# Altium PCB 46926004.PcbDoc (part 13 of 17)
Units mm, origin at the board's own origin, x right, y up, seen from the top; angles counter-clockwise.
Board outline 250 x 200 mm, 6 copper layers (Top Layer, INT1_GND, INT2_SIG, INT3_SIG, INT4_GND, Bottom Layer), stack 1.71 mm thick; 1450 components, 1293 nets, 5656 pads, 2307 vias.
Unrouted connection lines stored in the file: 2.
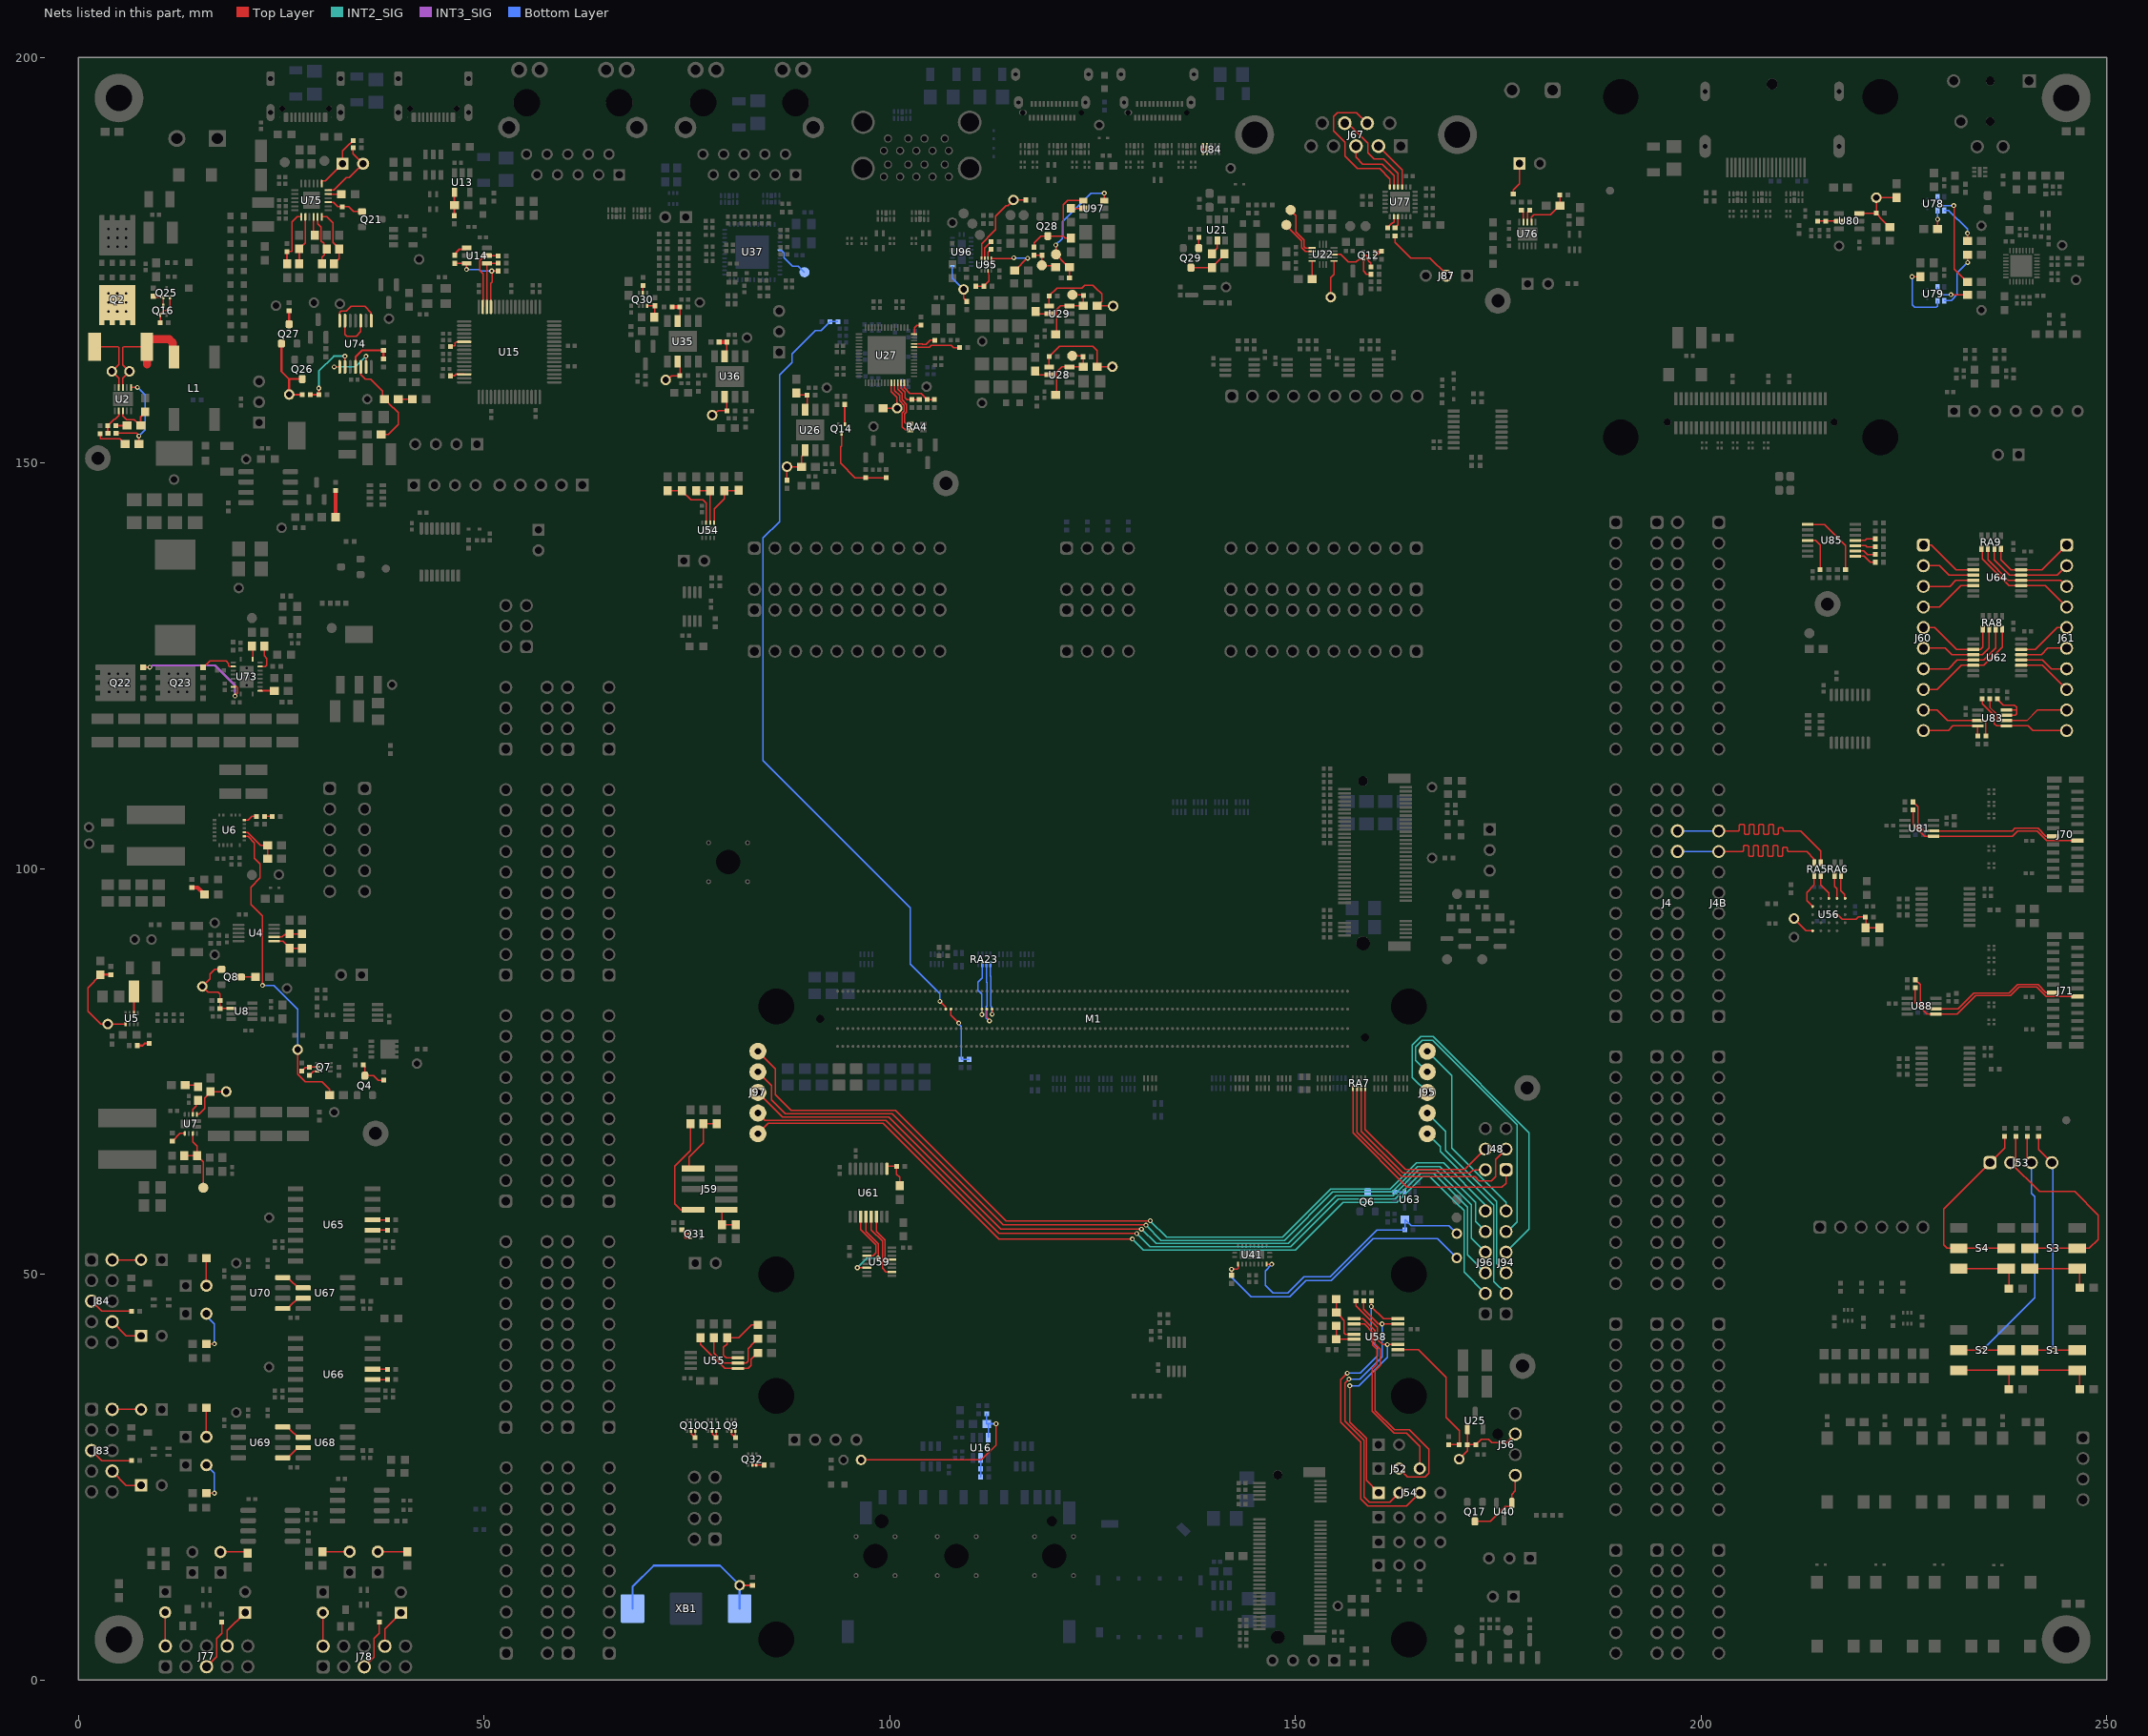
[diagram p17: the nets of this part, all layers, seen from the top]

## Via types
v1: diameter 0.6, hole 0.3, Top Layer to Bottom Layer, tented both sides, 2171 vias
v2: diameter 0.6, hole 0.3, Top Layer to Bottom Layer, 48 vias
v3: diameter 1, hole 0.5, Top Layer to Bottom Layer, tented both sides, 37 vias
v4: diameter 0.5, hole 0.2, Top Layer to Bottom Layer, tented both sides, 34 vias
v5: diameter 0.6, hole 0.3, Top Layer to Bottom Layer, tented bottom, 17 vias

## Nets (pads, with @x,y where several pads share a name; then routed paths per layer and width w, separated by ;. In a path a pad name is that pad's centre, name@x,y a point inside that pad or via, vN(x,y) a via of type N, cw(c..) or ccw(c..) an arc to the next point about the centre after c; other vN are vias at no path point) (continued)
NetJ45_2: J45.2 R206.2 | length 3.4
  Top Layer w0.15: R206.2@30.075,15.825 30.08,15.82 J45.2@33.434,15.82
NetJ48_1: J48.1 RA7.5 | length 29
  Top Layer w0.15: RA7.5@157.1,72.95 157.1,67.423 163.774,60.749 175.449,60.749 175.95,61.25 J48.1@175.95,62.895
NetJ48_2: J48.2 RA7.7 | length 22.9
  Top Layer w0.15: RA7.7@158.1,72.95 158.1,67.6 163.2,62.5 171.503,62.5 171.898,62.895 J48.2@173.41,62.895
NetJ48_3: J48.3 RA7.6 | length 29.1
  Top Layer w0.15: RA7.6@157.6,72.95 157.6,67.536 163.111,62.025 172.145,62.025 172.645,61.525 174.15,61.525 174.65,62.025 174.65,64.135 J48.3@175.95,65.435
NetJ48_4: J48.4 RA7.8 | length 23
  Top Layer w0.15: RA7.8@158.6,72.95 158.6,67.856 163.556,62.9 170.875,62.9 J48.4@173.41,65.435
NetJ49_2: J49.2 R207.2 | length 3.6
  Top Layer w0.15: J49.2@17.461,15.833 21.081,15.833 R207.2@21.086,15.838
NetJ52_2: J52.2 U58.9 | length 29.4
  Top Layer w0.15: U58.9@157.237,44.523 158.358,44.523 159.833,43.048 159.833,41.405 160.468,40.769 160.468,38.788 159.833,38.152 159.833,33.222 162.218,30.837 164.056,30.837 166.45,28.442 166.45,25.5 165.975,25.025 163.802,25.025 J52.2@162.777,26.05
NetJ52_3: J52.3 U58.10 | length 23.3
  Top Layer w0.15: U58.10@157.237,43.888 158.505,43.888 159.533,42.86 159.533,41.28 160.058,40.755 160.058,38.95 159.487,38.379 159.487,33.144 162.191,30.44 163.664,30.44 165.317,28.787 J52.3@165.317,26.05
NetJ53_1: J53.1 R259.2 S4.2 S4.5 | length 24.7
  Top Layer w0.15: S4.2@231.425,53.215 S4.5@237.925,53.215 ; S4.2@231.425,53.215 230.3,53.215 229.9,53.615 229.9,58.06 J53.1@235.615,63.775 237.4,65.56 R259.2@237.4,67
NetJ53_2: J53.2 R263.2 S3.2 S3.5 | length 29.2
  Top Layer w0.15: R263.2@238.8,67 238.8,64.42 J53.2@238.155,63.775 241.73,60.2 246.04,60.2 248.925,57.315 248.925,54.29 247.85,53.215 S3.2@240.175,53.215
NetJ53_3: J53.3 R257.2 S2.2 S2.5 | length 35.9
  Top Layer w0.15: S2.2@231.425,40.665 v1(234.675,40.665) S2.5@237.925,40.665 ; R257.2@240.2,67 240.2,64.27 J53.3@240.695,63.775
  Bottom Layer w0.15: v1(234.675,40.665) 241.125,47.115 241.125,59.55 240.695,59.98 J53.3@240.695,63.775
NetJ53_4: J53.4 R261.2 S1.2 S1.5 | length 33.6
  Top Layer w0.15: S1.2@240.175,40.665 S1.5@246.675,40.665 ; R261.2@241.6,67 241.6,65.41 J53.4@243.235,63.775
  Bottom Layer w0.15: J53.4@243.235,63.775 243.339,63.671 243.339,40.751 v1(243.425,40.665)
NetJ54_1: J54.1 R271.2 U58.3 | length 31
  Top Layer w0.15: v1(156.7,36.275) 156.7,31.811 158.736,29.775 158.736,24.589 J54.1@160.25,23.075 ; R271.2@157.461,46.743 157.461,46.139 160.133,43.467 160.133,41.952 160.738,41.347 v1(161.329,41.347) U58.3@162.637,41.347
  Bottom Layer w0.15: v1(156.7,36.275) 157.83,36.275 161.329,39.774 v1(161.329,41.347)
NetJ54_2: J54.2 R269.2 U58.7 | length 36.1
  Top Layer w0.15: v1(156.6,37.1) 156.114,36.614 156.114,31.893 158.436,29.571 158.436,22.589 159.1,21.925 161.64,21.925 J54.2@162.79,23.075 ; R269.2@158.411,46.743 158.411,45.71 160.233,43.888 U58.7@162.637,43.888
  Bottom Layer w0.15: v1(156.6,37.1) 157.956,37.1 160.681,39.825 v1(160.681,43.888)
NetJ54_3: J54.3 R268.2 U58.8 | length 40.8
  Top Layer w0.15: v1(156.383,37.824) 155.589,37.03 155.589,31.791 158.055,29.324 158.055,22.325 158.924,21.456 163.711,21.456 J54.3@165.33,23.075 ; R268.2@159.359,46.743 v1(159.359,46.033) 160.869,44.523 U58.8@162.637,44.523
  Bottom Layer w0.15: v1(156.383,37.824) 157.987,37.824 160.133,39.97 160.133,41.036 159.359,41.811 v1(159.359,46.033)
NetJ56_1: J56.1 Q17.3 U40.1 | length 9.2
  Top Layer w0.15: Q17.3@172.125,19.55 174.045,19.55 175.87,21.375 176.456,21.375 176.675,21.594 U40.1@176.675,21.8 176.675,22.875 177.1,23.3 J56.1@177.1,25.235
NetJ56_3: J56.3 R273.2 R274.1 U25.1 X80.1 | length 10.9
  Top Layer w0.15: X80.1@170.175,27.218 171.2,28.243 R273.2@171.2,29 ; U25.1@171.2,30.925 R273.2@171.2,29 ; J56.3@177.1,30.315 176.035,29.25 174.218,29.25 173.768,29.7 172.937,29.7 R274.1@172.237,29 R273.2@171.2,29
NetJ59_1: J59.1 R286.1 R287.1 | length 7.9
  Top Layer w0.15: J59.1@75.265,63.04 75.265,64.44 77.03,66.205 R286.1@77.03,68.55 R287.1@78.65,68.55
NetJ59_9: J59.9 R288.1 | length 12.7
  Top Layer w0.15: J59.9@75.265,57.96 74.24,57.96 73.5,58.7 73.5,63.358 75.425,65.283 R288.1@75.425,68.55
NetJ59_10: J59.10 R463.2 R464.2 | length 3.6
  Top Layer w0.15: J59.10@79.335,57.96 79.325,57.95 R464.2@79.325,56.1 R463.2@81.05,56.1
NetJ60_1: J60.1 U64.3 | length 7.1
  Top Layer w0.15: J60.1@227.4,139.88 228.395,139.88 231.425,136.85 U64.3@233.25,136.85
NetJ60_2: J60.2 U64.4 | length 6.3
  Top Layer w0.15: J60.2@227.4,137.34 229.385,137.34 230.525,136.2 U64.4@233.25,136.2
NetJ60_3: J60.3 U64.5 | length 6.2
  Top Layer w0.15: J60.3@227.4,134.8 230.65,134.8 231.4,135.55 U64.5@233.25,135.55
NetJ60_4: J60.4 U64.6 | length 6.9
  Top Layer w0.15: J60.4@227.4,132.26 229.385,132.26 232.025,134.9 U64.6@233.25,134.9
NetJ60_5: J60.5 RA8.1 U62.3 | length 10.8
  Top Layer w0.15: J60.5@227.4,129.72 228.78,129.72 231.475,127.025 233.25,127.025 234.425,127.025 234.712,127.312 RA8.1@234.712,129.525
NetJ60_6: J60.6 RA8.2 U62.4 | length 11.1
  Top Layer w0.15: J60.6@227.4,127.18 230.07,127.18 230.875,126.375 233.25,126.375 234.675,126.375 235.512,127.212 RA8.2@235.512,129.525
NetJ60_7: J60.7 RA8.3 U62.5 | length 12.3
  Top Layer w0.15: J60.7@227.4,124.64 230.49,124.64 231.575,125.725 233.25,125.725 234.85,125.725 236.312,127.187 RA8.3@236.312,129.525
NetJ60_8: J60.8 RA8.4 U62.6 | length 14.1
  Top Layer w0.15: J60.8@227.4,122.1 229.1,122.1 232.075,125.075 233.25,125.075 234.85,125.075 237.112,127.337 RA8.4@237.112,129.525
NetJ60_9: J60.9 R442.2 U83.3 | length 10.1
  Top Layer w0.15: J60.9@227.4,119.56 229.065,119.56 230.375,118.25 U83.3@234.105,118.25 234.107,118.248 234.952,118.248 235.1,118.1 R442.2@235.1,116.35
NetJ60_10: J60.10 R443.2 U83.4 | length 8.2
  Top Layer w0.15: J60.10@227.4,117.02 230.47,117.02 231.05,117.6 U83.4@234.105,117.6 234.105,116.355 R443.2@234.1,116.35
NetJ61_1: J61.1 RA9.4 U64.14 | length 11.2
  Top Layer w0.15: RA9.4@236.95,139.425 236.95,138.1 238.2,136.85 239.75,136.85 242.02,136.85 J61.1@245.05,139.88
NetJ61_2: J61.2 RA9.3 U64.13 | length 11.5
  Top Layer w0.15: RA9.3@236.15,139.425 236.15,138.05 238,136.2 239.75,136.2 243.91,136.2 J61.2@245.05,137.34
NetJ61_3: J61.3 RA9.2 U64.12 | length 12.4
  Top Layer w0.15: RA9.2@235.35,139.425 235.35,138.05 237.85,135.55 239.75,135.55 244.3,135.55 J61.3@245.05,134.8
NetJ61_4: J61.4 RA9.1 U64.11 | length 14.1
  Top Layer w0.15: RA9.1@234.55,139.425 234.653,139.322 234.653,138.216 237.969,134.9 239.75,134.9 242.41,134.9 J61.4@245.05,132.26
NetJ61_5: J61.5 U62.14 | length 6.4
  Top Layer w0.15: U62.14@239.75,127.025 241.175,127.025 243.87,129.72 J61.5@245.05,129.72
NetJ61_6: J61.6 U62.13 | length 5.6
  Top Layer w0.15: U62.13@239.75,126.375 241.925,126.375 242.73,127.18 J61.6@245.05,127.18
NetJ61_7: J61.7 U62.12 | length 5.7
  Top Layer w0.15: U62.12@239.75,125.725 242.075,125.725 243.16,124.64 J61.7@245.05,124.64
NetJ61_8: J61.8 U62.11 | length 6.5
  Top Layer w0.15: U62.11@239.75,125.075 242.075,125.075 J61.8@245.05,122.1
NetJ61_9: J61.9 R446.2 U83.6 | length 12.1
  Top Layer w0.18: R446.2@235.578,120.925 235.578,119.897 236.5,118.975 236.5,118.375 236.625,118.25 U83.6@237.645,118.25 240.15,118.25 241.46,119.56 J61.9@245.05,119.56
NetJ61_10: J61.10 R445.2 U83.5 | length 12.9
  Top Layer w0.15: R445.2@234.653,120.925 234.653,120.322 236.125,118.85 236.125,117.875 236.4,117.6 U83.5@237.645,117.6 240.325,117.6 240.905,117.02 J61.10@245.05,117.02
NetJ64_2: J64.2 R208.2 | length 3.6
  Top Layer w0.15: J64.2@36.9,15.82 40.52,15.82 R208.2@40.525,15.825
NetJ66_1: J66.1 R350.1 | length 4.1
  Top Layer w0.15: R350.1@176.855,183.15 176.855,183.682 177.605,184.432 J66.1@177.605,186.925
NetJ67_2: J67.2 U77.3 | length 6.1
  Top Layer w0.15: J67.2@160.235,189.06 163.15,186.145 U77.3@163.15,184.215
NetJ67_3: J67.3 U77.5 | length 8.2
  Top Layer w0.15: J67.3@157.465,189.06 157.465,187.697 158.302,186.86 160.714,186.86 162.15,185.424 U77.5@162.15,184.215
NetJ67_7: J67.7 U77.6 | length 17.9
  Top Layer w0.15: J67.7@158.85,191.9 157.54,193.21 155.171,193.21 154.695,192.734 154.695,190.946 156.121,189.52 156.121,187.817 157.651,186.287 160.398,186.287 161.65,185.035 U77.6@161.65,184.215
NetJ67_8: J67.8 U77.4 | length 11.3
  Top Layer w0.15: J67.8@156.08,191.9 156.484,191.9 158.95,189.434 158.95,188.247 159.697,187.5 160.849,187.5 162.65,185.699 U77.4@162.65,184.215
NetJ68_2: J68.2 R293.2 | length 4.9
  Top Layer w0.15: R293.2@15.77,41.447 R293.2@15.775,41.442 ; R293.2@15.773,41.445 v1(16.773,41.445)
  Bottom Layer w0.15: J68.2@15.77,44.9 16.773,43.898 v1(16.773,41.445)
NetJ70_13: J70.13 R364.2 U81.6 | length 20.6
  Top Layer w0.15: R364.2@226.12,108.23 226.724,107.625 226.724,105.416 227.475,104.665 U81.6@228.66,104.665 238.336,104.665 238.641,104.97 241.516,104.97 242.496,103.99 J70.13@243.4,103.99
NetJ70_14: J70.14 R365.2 U81.5 | length 23.4
  Top Layer w0.15: R365.2@226.12,107.24 226.12,105.435 227.54,104.015 U81.5@228.66,104.015 238.358,104.015 239.013,104.67 241.392,104.67 242.572,103.49 J70.14@246.4,103.49
NetJ71_13: J71.13 R372.2 U88.6 | length 21.4
  Top Layer w0.15: R372.2@226.404,86.305 227.009,85.7 227.009,83.491 227.759,82.74 U88.6@228.944,82.74 231.684,82.74 233.624,84.68 237.968,84.68 239.019,85.731 241.514,85.731 242.493,84.751 243.379,84.751 J71.13@243.4,84.73
NetJ71_14: J71.14 R373.2 U88.5 | length 24.3
  Top Layer w0.15: R373.2@226.404,85.315 226.404,83.51 227.825,82.09 U88.5@228.944,82.09 231.559,82.09 233.849,84.38 238.15,84.38 239.201,85.431 241.333,85.431 242.519,84.245 246.385,84.245 J71.14@246.4,84.23
NetJ73_2: J73.2 R295.2 | length 4.9
  Top Layer w0.15: R295.2@15.77,23.03 R295.2@15.775,23.025 ; R295.2@15.772,23.028 v1(16.772,23.028)
  Bottom Layer w0.15: J73.2@15.77,26.483 16.772,25.481 v1(16.772,23.028)
NetJ74_2: J74.2 R294.2 | length 3.6
  Top Layer w0.15: J74.2@15.77,48.383 15.77,51.962 R294.2@15.775,51.967
NetJ75_2: J75.2 R296.2 | length 3.6
  Top Layer w0.15: J75.2@15.77,29.966 15.77,33.545 R296.2@15.775,33.55
NetJ77_2: J77.2 J79.2 | length 4.1
  Top Layer w0.15: J79.2@10.686,8.318 10.701,8.303 10.701,4.198 J77.2@10.716,4.183
NetJ77_5: J77.5 R357.1 | length 6.3
  Top Layer w0.15: J77.5@15.796,1.643 17.011,2.858 17.011,5.113 17.661,5.763 R357.1@17.661,7.138
NetJ77_8: J77.8 J80.1 | length 5
  Top Layer w0.15: J77.8@18.336,4.183 18.336,6.098 J80.1@20.551,8.313
NetJ78_2: J78.2 J81.2 | length 4.1
  Top Layer w0.15: J81.2@30.125,8.305 30.14,8.29 30.14,4.185 J78.2@30.155,4.17
NetJ78_5: J78.5 R356.1 | length 6.3
  Top Layer w0.15: J78.5@35.235,1.63 36.45,2.845 36.45,5.1 37.1,5.75 R356.1@37.1,7.125
NetJ78_8: J78.8 J82.1 | length 4.9
  Top Layer w0.15: J78.8@37.775,4.17 37.775,6.3 J82.1@39.75,8.275
NetJ83_2: J83.2 J85.2 | length 3.6
  Top Layer w0.15: J83.2@4.163,33.363 4.169,33.356 7.723,33.356 J85.2@7.73,33.35
NetJ83_5: J83.5 R380.1 | length 5.4
  Top Layer w0.15: J83.5@1.623,28.283 2.856,27.05 R380.1@6.55,27.05
NetJ83_8: J83.8 J86.1 | length 4.3
  Top Layer w0.15: J83.8@4.163,25.743 5.906,24 J86.1@7.73,24
NetJ84_2: J84.2 J89.2 | length 3.6
  Top Layer w0.15: J84.2@4.163,51.78 4.173,51.79 7.72,51.79 J89.2@7.73,51.8
NetJ84_5: J84.5 R381.1 | length 5.4
  Top Layer w0.15: J84.5@1.623,46.7 2.856,45.467 R381.1@6.55,45.467
NetJ84_8: J84.8 J90.1 | length 4.3
  Top Layer w0.15: J84.8@4.163,44.16 5.906,42.417 J90.1@7.73,42.417
NetJ87_2: J87.2 R382.2 | length 8.9
  Top Layer w0.15: R382.2@162.275,178 162.275,177.224 164.234,175.265 166.59,175.265 168.6,173.255 J87.2@168.6,173.1
NetJ88_1: J88.1 R403.2 U75.13 | length 7.2
  Top Layer w0.15: U75.13@29.975,184.45 29.975,184.737 30.025,184.787 30.442,184.787 J88.1@32.555,186.9 32.555,188.473 33.457,189.375 33.475,189.375 R403.2@33.85,189.75
NetJ88_2: J88.2 R402.2 U75.12 | length 8.1
  Top Layer w0.15: U75.12@30.775,183.65 31.498,183.65 33.019,185.171 33.366,185.171 J88.2@35.095,186.9 33.85,188.145 R402.2@33.85,188.85
NetJ94_2: J94.2 J95.1 | length 23.7
  INT2_SIG w0.15: J95.1@166.25,67.34 167.847,65.743 167.847,65.153 174.469,58.531 174.469,49.136 J94.2@175.95,47.655
NetJ94_3: J94.3 J95.2 | length 23.7
  INT2_SIG w0.15: J95.2@166.25,69.88 168.506,67.624 168.506,65.29 174.8,58.996 174.8,51.345 J94.3@175.95,50.195
NetJ94_4: J94.4 J95.3 | length 42.2
  INT2_SIG w0.15: J95.3@166.25,72.42 164.4,74.27 164.4,78.256 165.436,79.292 166.98,79.292 178.8,67.471 178.8,55.585 J94.4@175.95,52.735
NetJ94_5: J94.5 J95.4 | length 34.7
  INT2_SIG w0.15: J95.4@166.25,74.96 164.8,76.41 164.8,78.05 165.624,78.874 166.906,78.874 177.34,68.44 177.34,56.49 176.125,55.275 J94.5@175.95,55.275
NetJ94_6: J94.6 J95.5 | length 23.7
  INT2_SIG w0.15: J95.5@166.25,77.5 169.25,74.5 169.25,65.55 175.95,58.85 J94.6@175.95,57.815
NetJ96_2: J96.2 J97.1 | length 110.8
  Top Layer w0.15: J97.1@83.75,67.34 85.024,68.614 99.187,68.614 113.434,54.367 v1(129.888,54.367)
  INT2_SIG w0.15: v1(129.888,54.367) 131.255,53 149.989,53 155.856,58.867 162.502,58.867 165.696,62.06 166.586,62.06 169.875,58.771 170.8,57.846 170.8,50.265 J96.2@173.41,47.655
NetJ96_3: J96.3 J97.2 | length 108.8
  Top Layer w0.15: J97.2@83.75,69.88 84.63,69 99.506,69 113.48,55.026 v1(130.45,55.026)
  INT2_SIG w0.15: v1(130.45,55.026) 132.076,53.4 149.426,53.4 155.312,59.285 162.289,59.285 165.449,62.446 167.054,62.446 171.2,58.3 171.2,52.405 J96.3@173.41,50.195
NetJ96_4: J96.4 J97.3 | length 107.7
  Top Layer w0.15: J97.3@83.75,72.42 86.77,69.4 99.893,69.4 113.718,55.575 v1(131.022,55.575)
  INT2_SIG w0.15: v1(131.022,55.575) 131.042,55.575 132.817,53.8 149.119,53.8 155.019,59.7 162.017,59.7 165.173,62.855 167.396,62.855 171.658,58.594 171.658,54.487 J96.4@173.41,52.735
NetJ96_5: J96.5 J97.4 | length 107.7
  Top Layer w0.15: J97.4@83.75,74.96 85.455,73.255 85.455,71.506 87.161,69.8 100.313,69.8 113.996,56.116 131.539,56.116 v1(131.583,56.072)
  INT2_SIG w0.15: v1(131.583,56.072) v1(131.583,56.072) 133.457,54.2 148.648,54.2 154.596,60.148 161.91,60.148 165.022,63.26 167.81,63.26 172.19,58.88 172.19,56.495 J96.5@173.41,55.275
NetJ96_6: J96.6 J97.5 | length 107.7
  Top Layer w0.15: J97.5@83.75,77.5 85.9,75.35 85.9,72.154 87.854,70.2 100.725,70.2 114.316,56.609 v1(132.108,56.609)
  INT2_SIG w0.15: v1(132.108,56.609) 134.116,54.6 148.412,54.6 154.329,60.517 161.719,60.517 164.945,63.743 168.257,63.743 173.41,58.59 J96.6@173.41,57.815
NetL1_2: L1.2 R8.1 U2.8 X109.1 | length 16.9
  Top Layer w0.15: U2.8@5.477,159.334 5.477,160.484 X109.1@6.293,161.3 5.477,162.116 5.477,164.259 5.565,164.347 R8.1@8.448,164.347
  Top Layer w1: 8.448,162.147 R8.1@8.448,164.347 8.448,165.247 11.204,165.247 11.65,164.801 11.65,163.212 L1.2@11.79,163.072
NetL5_1: L5.1 U5.6 | length 2.7
  Top Layer w0.25: U5.6@6.825,82.197 L5.1@6.825,84.85
NetM1_B78: M1.B78 R66.2 R459.2 | length 7.7
  Top Layer w0.15: M1.B78@107.537,82.7 107.537,81.94 v1(108.5,80.977)
  Bottom Layer w0.15: v1(108.5,80.977) 108.5,80.856 108.807,80.549 R66.2@108.807,76.507 ; R66.2@108.8,76.5 108.9,76.5 R459.2@109.8,76.5
NetM1_B79: M1.B79 R65.2 R352.1 | length 98.9
  Top Layer w0.15: v1(106.181,83.658) 106.886,82.954 106.886,82.716 M1.B79@106.902,82.7
  Bottom Layer w0.15: R65.2@93.622,167.443 R352.1@92.649,167.443 91.567,166.36 90.847,166.36 87.947,163.46 87.947,162.391 86.426,160.87 86.426,142.776 84.4,140.75 84.4,113.324 102.539,95.185 102.539,88.25 106.181,84.607 v1(106.181,83.658)
NetQ2_5: Q2.5 Q2.6 Q2.7 Q2.8 R8.2 U2.9 X108.1 | length 14.4
  Top Layer w0.15: R8.2@1.998,164.347 4.889,164.347 4.977,164.259 4.977,162.154 X108.1@4.123,161.3 4.977,160.446 U2.9@4.977,159.334
  Top Layer w0.25: Q2.5@2.89,167.324 Q2.5@2.89,167.371 2.89,168.059 3.187,168.357 3.548,168.357 3.595,168.404 4.096,167.903 4.096,167.388 Q2.6@4.16,167.324 ; Q2.8@4.79,168.404 5.328,167.866 5.328,167.426 Q2.7@5.43,167.324 ; Q2.8@5.985,168.404 6.052,168.337 6.313,168.337 6.7,167.95 Q2.8@6.7,167.371 Q2.8@6.7,167.324
NetQ4_3: Q4.3 R19.1 R20.1 | length 4
  Top Layer w0.15: R20.1@35.125,75.8 35.3,75.625 Q4.3@35.3,74.475 36.38,74.475 36.935,73.92 R19.1@37.65,73.92
NetQ6_3: Q6.3 R181.1 U63.1 | length 4.4
  Bottom Layer w0.15: Q6.3@159.039,60.148 R181.1@162.231,60.148 U63.1@163.45,60.148
NetQ7_5: Q7.5 R53.2 R57.1 | length 2.1
  Top Layer w0.15: R53.2@27.55,75.05 27.987,75.487 28.409,75.487 R57.1@28.472,75.55 Q7.5@29.46,75.55
NetQ7_6: Q7.6 R57.2 | length 1.2
  Top Layer w0.15: R57.2@28.472,74.55 28.972,75.05 Q7.6@29.46,75.05
NetQ8_1: Q8.1 R58.1 R59.2 U8.6 X28.1 | length 9.3
  Top Layer w0.15: Q8.1@17.65,87.6 16.8,87.6 16.235,87.035 16.235,86.447 X28.1@15.275,85.487 15.962,84.8 17.2,84.8 17.45,84.55 R59.2@17.45,83.775 R58.1@17.45,82.775 U8.6@18.835,82.775
NetQ8_3: Q8.3 R64.1 | length 1.8
  Top Layer w0.15: Q8.3@20.05,86.65 R64.1@21.825,86.65
NetQ9_2: Q9.2 Q9.3 R92.2 | length 1.8
  Top Layer w0.15: Q9.2@80.475,30.7 80.513,30.662 80.513,30.345 80.75,30.109 R92.2@80.975,29.884 ; R92.2@80.975,29.962 Q9.3@80.975,30.7
NetQ10_2: Q10.2 Q10.3 R93.2 | length 1.8
  Top Layer w0.15: Q10.2@75.509,30.681 75.535,30.655 75.535,30.319 75.765,30.09 75.784,30.09 75.999,29.875 R93.2@75.999,29.855 ; R93.2@76.009,29.943 Q10.3@76.009,30.681
NetQ11_2: Q11.2 Q11.3 R94.2 | length 1.7
  Top Layer w0.15: Q11.2@78.095,30.7 78.133,30.662 78.133,30.345 78.517,29.962 78.595,29.962 Q11.3@78.595,30.7
NetQ12_2: Q12.2 R111.1 | length 2.1
  Top Layer w0.15: Q12.2@158.396,175.615 158.758,175.615 158.846,175.527 158.846,175.059 159.165,174.74 159.208,174.74 159.296,174.652 R111.1@159.296,174.165
NetQ12_3: Q12.3 R116.2 U22.11 | length 6.7
  Top Layer w0.15: U22.11@154.746,175.715 155.61,175.715 156.51,174.815 157.486,174.815 157.786,175.115 Q12.3@158.396,175.115 158.396,173.65 158.781,173.265 R116.2@159.296,173.265
NetQ12_5: Q12.5 Q12.6 R113.2 | length 1.9
  Top Layer w0.15: Q12.5@159.746,175.615 159.809,175.678 160.159,175.678 R113.2@160.596,176.115 Q12.6@159.746,176.115
NetQ14_1: Q14.1 R136.1 | length 2.4
  Top Layer w0.25: Q14.1@94.47,154.781 R136.1@94.47,157.23
NetQ14_3: Q14.3 R135.1 R137.1 | length 10.1
  Top Layer w0.15: Q14.3@94.07,153.638 94.07,152.129 93.922,151.982 93.922,149.971 95.695,148.198 R137.1@97.046,148.198 R135.1@99.558,148.198
NetQ16_1: Q16.1 Q25.2 R347.1 | length 3.8
  Top Layer w0.15: R347.1@10.075,167.28 10.08,167.285 Q16.1@10.08,168.256 10.08,168.37 10.5,168.79 10.843,168.79 11.28,169.227 Q25.2@11.28,170.42
NetQ16_3: Q16.3 Q25.1 R9.1 | length 2.3
  Top Layer w0.15: R9.1@9.225,170.565 9.37,170.42 Q25.1@10.48,170.42 Q16.3@10.48,169.399
NetQ21_1: Q21.1 R317.2 U75.9 | length 4.7
  Top Layer w0.15: U75.9@30.775,182.15 31.425,182.15 31.975,181.6 R317.2@32.5,181.6 33.325,181.6 33.925,181 Q21.1@34.95,181
NetQ22_4: Q22.4 U73.18 | length 15.5
  Top Layer w0.15: Q22.4@7.98,124.83 v1@8.797,124.83 ; U73.18@19.092,122.425 19.55,122.425 19.642,122.333 19.642,122.039 19.642,121.685 19.305,121.348 v1(19.305,121.28)
  INT3_SIG w0.25: v1(8.802,124.835) 8.897,124.835 9.122,125.06 16.831,125.06 19.305,122.586 v1(19.305,121.28)
NetQ23_4: Q23.4 U73.13 | length 4.5
  Top Layer w0.15: Q23.4@15.365,124.825 15.443,124.825 16.218,125.6 18.203,125.6 18.525,125.277 18.525,125.013 18.613,124.925 U73.13@19.092,124.925
NetQ26_3: Q26.3 Q27.1 R313.1 X113.1 | length 9.9
  Top Layer w0.25: Q27.1@25.025,164.725 25.025,161.294 25.975,160.344 ; R313.1@27.6,158.45 X113.1@25.975,158.45 25.975,160.344 ; Q26.3@27.6,160.356 25.987,160.356 25.975,160.344
NetQ27_3: Q27.3 R316.2 | length 1.6
  Top Layer w0.25: Q27.3@25.975,167.125 R316.2@25.975,168.775
NetQ28_3: Q28.3 R390.1 R434.2 U97.4 | length 12.1
  Top Layer w0.15: R434.2@117.795,176.611 117.795,177.142 118.645,177.992 Q28.3@119.467,177.992 121.376,177.992 ; R390.1@122.321,177.721 121.647,177.721 121.376,177.992 ; U97.4@123.858,182.348 121.894,182.348 121.376,181.83 121.376,177.992
NetQ29_1: Q29.1 R395.2 | length 1.4
  Top Layer w0.15: Q29.1@138.08,176.486 R395.2@138.08,177.838
NetQ29_3: Q29.3 R101.1 R112.2 | length 4.9
  Top Layer w0.15: Q29.3@137.13,174.086 R112.2@139.712,174.086 139.712,174.136 140.845,175.268 140.845,175.361 R101.1@141.27,175.786
NetQ30_2: Q30.2 R121.1 | length 0.9
  Top Layer w0.15: Q30.2@69.576,170.969 R121.1@69.576,171.89
NetQ30_6: Q30.6 R61.2 R63.2 | length 2.4
  Top Layer w0.15: Q30.6@70.076,169.389 R63.2@71.051,169.389 71.051,168.061 R61.2@70.95,167.96
NetQ31_5: Q31.5 Q31.6 R458.2 | length 2.5
  Top Layer w0.15: R458.2@74.384,55.475 74.652,55.206 74.652,54.975 ; Q31.6@75.35,54.475 74.74,54.475 74.652,54.563 74.652,54.975 ; Q31.5@75.35,54.975 74.652,54.975
NetQ32_2: Q32.2 Q32.3 R467.2 | length 1.5
  Top Layer w0.15: Q32.2@83.075,26.5 Q32.3@83.575,26.5 84.475,26.5 R467.2@84.525,26.55
NetR1_1: R1.1 R4.1 U2.2 | length 3.5
  Top Layer w0.15: R4.1@3.634,154.62 4.409,155.395 4.521,155.395 4.977,155.851 U2.2@4.977,156.438
  Top Layer w0.25: R1.1@3.634,153.581 R4.1@3.634,154.62
NetR1_2: R1.2 R6.1 U2.6 | length 11.5
  Top Layer w0.15: R1.2@4.641,153.672 7.14,153.672 7.453,153.36 7.453,152.384 R6.1@7.473,152.364 ; U2.6@6.477,159.334 v1(7.27,159.334)
  Bottom Layer w0.15: v1(7.27,159.334) 8.227,158.377 8.227,154.111 v1(7.453,153.337)
NetR2_1: R2.1 R3.2 U2.3 | length 5.2
  Top Layer w0.15: U2.3@5.477,156.438 5.477,155.824 5.936,155.365 6.889,155.365 7.634,154.62 R2.1@7.684,154.62
  Top Layer w0.25: R2.1@7.684,154.62 7.684,155.718 8.227,156.262 R3.2@8.227,156.312
NetR2_2: R2.2 R4.2 | length 1.3
  Top Layer w0.25: R4.2@4.634,154.62 R2.2@5.984,154.62
NetR5_1: R5.1 R6.2 | length 3.9
  Top Layer w0.15: R5.1@2.676,153.627 2.676,153.073 2.763,152.985 5.102,152.985 5.723,152.364 R6.2@5.773,152.364
NetR15_2: R15.2 R18.2 U4.1 | length 3.8
  Top Layer w0.15: U4.1@24.125,91.074 25.181,91.074 25.605,90.65 25.617,90.65 26.042,90.225 R18.2@26.042,90.175 R15.2@27.55,90.175
NetR16_2: R16.2 R17.2 U4.2 | length 3.6
  Top Layer w0.15: U4.2@24.125,91.574 25.099,91.574 25.413,91.888 25.963,91.888 R16.2@26.05,91.975 R17.2@27.55,91.975
NetR27_1: R27.1 R38.1 U5.1 X13.1 | length 11.8
  Top Layer w0.15: R38.1@2.725,86.95 2.725,86.9 1.15,85.325 1.15,82.45 2.75,80.85 5.822,80.85 U5.1@5.825,80.847
  Top Layer w0.25: R38.1@2.725,86.95 R27.1@4,86.95
NetR28_1: R28.1 U6.2 X14.1 | length 39.5
  Top Layer w0.15: U6.2@20.445,103.988 20.903,103.988 21.691,103.2 21.691,101.275 22.403,100.563 22.403,98.858 21.275,97.731 21.275,95.615 22.688,94.202 v1(22.688,85.616) ; X14.1@27.025,77.7 27.025,74.657 27.953,73.728 30.022,73.728 30.95,72.8 R28.1@30.95,72.075
  Bottom Layer w0.15: v1(22.688,85.616) 24.084,85.616 27.025,82.675 X14.1@27.025,77.7
NetR29_1: R29.1 R30.2 | length 1.6
  Top Layer w0.25: R30.2@7.248,78.2 7.925,78.2 8.175,78.45 R29.1@8.725,78.45
NetR32_2: R32.2 R34.2 U6.3 | length 5.2
  Top Layer w0.15: U6.3@20.445,104.488 20.852,104.488 22.434,102.907 R32.2@23.341,102.907 23.345,102.902 R34.2@23.345,101.232
NetR33_2: R33.2 U7.7 X15.1 | length 5.6
  Top Layer w0.15: U7.7@14.609,69.717 14.638,69.746 14.871,69.746 15.56,70.435 15.56,71.735 16.3,72.475 R33.2@16.3,72.525 X15.1@18.225,72.525
NetR35_1: R35.1 R36.2 | length 0.9
  Top Layer w0.15: R36.2@22.95,106.45 R35.1@23.9,106.45
NetR36_1: R36.1 U6.6 | length 1.7
  Top Layer w0.15: U6.6@20.445,105.989 20.914,105.989 21.375,106.45 R36.1@21.95,106.45
NetR37_1: R37.1 U7.1 | length 1.9
  Top Layer w0.15: R37.1@11.575,66.4 12.543,67.367 U7.1@13.109,67.367
NetR41_1: R41.1 U7.8 | length 2
  Top Layer w0.15: U7.8@14.109,69.717 14.109,70.357 14.49,70.738 14.49,71.14 R41.1@14.775,71.425
NetR41_2: R41.2 R42.1 | length 1.7
  Top Layer w0.15: R42.1@13.175,73.35 14.55,73.35 R41.2@14.775,73.125
NetR45_1: R45.1 R46.2 | length 1.9
  Top Layer w0.5: R45.1@13.991,97.675 14.691,97.675 R46.2@15.541,96.825
NetR48_2: R48.2 R49.2 U7.3 X20.1 | length 8.9
  Top Layer w0.15: R49.2@13.052,64.65 R48.2@14.627,64.65 14.627,65.8 14.109,66.317 14.109,67.267 U7.3@14.059,67.317 ; R49.2@13.053,64.424 R49.2@13.102,64.473 ; R48.2@14.627,64.65 14.628,64.599 15.052,64.175 15.103,64.175 15.403,63.875 X20.1@15.403,60.674
NetR84_2: R84.2 R85.2 U13.4 | length 2.9
  Top Layer w0.25: R85.2@46.341,180.494 U13.4@46.341,183.388
NetR86_2: R86.2 U14.5 U15.63 | length 8.4
  Top Layer w0.15: U15.63@49.85,169.25 49.865,169.265 49.865,173.35 49.465,173.75 49.465,174.991 50.04,175.566 U14.5@50.355,175.566 51.724,175.566 R86.2@51.74,175.55
NetR87_2: R87.2 U14.4 U15.62 | length 6.8
  Top Layer w0.15: U15.62@50.35,169.25 50.35,174.611 U14.4@50.355,174.616 51.731,174.616 R87.2@51.74,174.625
NetR88_1: R88.1 R89.2 U14.3 U15.61 | length 10.7
  Top Layer w0.15: R88.1@46.39,174.612 46.395,174.616 U14.3@47.845,174.616 v1(47.845,173.866) ; U15.61@50.85,169.25 50.85,172.163 50.99,172.303 50.99,173.624 v1(50.939,173.675) R89.2@51.74,173.675
  Bottom Layer w0.15: v1(47.845,173.866) 49.411,173.866 49.602,173.675 v1(50.939,173.675)
NetR88_2: R88.2 U14.1 | length 1.9
  Top Layer w0.25: R88.2@46.39,175.612 46.565,175.787 46.565,175.977 46.94,176.351 47.68,176.351 U14.1@47.845,176.516
NetR90_2: R90.2 U15.14 | length 1.8
  Top Layer w0.25: R90.2@45.84,160.75 45.869,160.779 46.369,160.779 46.53,160.94 47.54,160.94 U15.14@47.55,160.95
NetR91_2: R91.2 U15.6 | length 2.1
  Top Layer w0.15: R91.2@45.84,164.35 45.931,164.44 46.337,164.44 46.425,164.528 46.425,164.785 46.58,164.94 47.54,164.94 U15.6@47.55,164.95
NetR96_2: R96.2 R210.1 U16.3 X31.1 | length 24.2
  Top Layer w0.18: X31.1@96.467,27.133 111.283,27.133 113.1,28.95 v1(113.1,31.58)
  Bottom Layer w0.18: R210.1@111.95,32.835 R96.2@111.95,31.58 ; U16.3@112.15,29.88 112.15,31.38 R96.2@111.95,31.58 ; v1(113.1,31.58) R96.2@111.95,31.58
NetR97_2: R97.2 R98.2 U16.5 | length 2.3
  Bottom Layer w0.18: R98.2@111.194,25.035 111.2,25.041 U16.5@111.2,27.37
NetR107_2: R107.2 U22.5 | length 2.3
  Top Layer w0.15: R107.2@152.046,172.665 U22.5@152.046,174.915
NetR112_1: R112.1 U21.5 | length 1.9
  Top Layer w0.15: R112.1@139.712,175.786 139.712,175.836 140.37,176.493 U21.5@140.37,177.436
NetR124_2: R124.2 R213.1 U26.2 X43.1 | length 5.7
  Top Layer w0.15: R213.1@87.32,147.886 87.33,147.897 X43.1@87.33,149.549 R124.2@89.126,149.549 89.126,150.799 89.556,151.229 U26.2@89.556,151.581
NetR125_1: R125.1 R126.2 U27.40 | length 3.9
  Top Layer w0.15: U27.40@101.394,159.891 101.394,159.236 101.9,158.729 101.9,158.027 102.09,157.837 R125.1@102.737,157.837 R126.2@103.646,157.837
NetR127_2: R127.2 R128.1 U27.41 | length 4.9
  Top Layer w0.15: U27.41@101.794,159.891 101.794,159.26 102.494,158.56 103.873,158.56 R128.1@104.596,157.837 R127.2@105.495,157.837
NetR129_1: R129.1 R130.1 U26.7 | length 3.4
  Top Layer w0.15: R130.1@88.481,158.654 88.754,158.381 R129.1@89.826,158.381 89.826,156.851 U26.7@89.556,156.581
NetR131_2: R131.2 U27.37 X46.1 | length 4.8
  Top Layer w0.15: R131.2@99.494,156.762 X46.1@100.907,156.762 100.907,158.106 100.194,158.819 U27.37@100.194,159.891
NetR132_2: R132.2 U27.56 | length 1.8
  Top Layer w0.15: U27.56@102.995,165.893 103.048,165.893 103.075,165.92 103.075,166.7 103.371,166.996 R132.2@103.872,166.996
NetR133_2: R133.2 U27.52 | length 5.8
  Top Layer w0.15: U27.52@102.995,164.293 103.002,164.3 104.861,164.3 105.086,164.525 107.597,164.525 107.897,164.225 R133.2@108.602,164.225
NetR138_1: R138.1 R220.1 R355.2 U28.3 X48.1 | length 9
  Top Layer w0.15: R138.1@120.454,158.4 120.583,158.529 120.583,161.232 121.191,161.84 U28.3@122.154,161.84 123.809,161.84 R355.2@123.841,161.872 123.841,163.086 R220.1@123.822,163.104 123.7,163.226 X48.1@122.484,163.226
NetR139_1: R139.1 R298.1 R354.2 U29.3 X49.1 | length 9.3
  Top Layer w0.15: R139.1@120.461,165.863 120.562,165.965 120.562,168.921 121.005,169.363 U29.3@122.154,169.363 R354.2@123.861,169.363 R298.1@123.861,170.646 123.77,170.736 X49.1@122.511,170.736
NetR140_2: R140.2 R355.1 U28.4 X50.1 | length 11.8
  Top Layer w0.15: U28.4@119.644,161.84 119.644,163.13 R140.2@119.654,163.14 120.909,164.395 125.009,164.395 125.541,163.863 R355.1@125.541,161.872 X50.1@127.444,161.872
NetR141_2: R141.2 R354.1 U29.4 X51.1 | length 12.4
  Top Layer w0.15: U29.4@119.644,169.363 R141.2@119.644,170.613 120.617,171.586 123.704,171.586 124.045,171.928 125.043,171.928 125.382,171.59 125.382,171.586 126.137,170.831 126.137,169.89 R354.1@125.611,169.363 ; R354.1@125.561,169.363 R354.1@125.611,169.363 ; X51.1@127.536,169.363 R354.1@125.611,169.363
NetR142_2: R142.2 U28.5 | length 1.9
  Top Layer w0.15: R142.2@117.898,161.34 117.898,161.315 118.323,160.89 U28.5@119.644,160.89
NetR143_2: R143.2 U29.5 | length 1.8
  Top Layer w0.15: R143.2@117.975,168.703 118.265,168.413 U29.5@119.644,168.413
NetR165_2: R165.2 U35.2 X54.1 | length 3.8
  Top Layer w0.15: X54.1@72.385,160.248 72.538,160.248 73.07,160.78 R165.2@74.12,160.78 74.12,161.887 73.855,162.152 U35.2@73.855,162.504
NetR166_2: R166.2 U36.2 X55.1 | length 3.8
  Top Layer w0.15: X55.1@78.19,155.911 78.343,155.911 78.875,156.442 R166.2@79.925,156.442 79.925,157.55 79.66,157.815 U36.2@79.66,158.167
NetR169_1: R169.1 R172.2 U35.7 | length 2.8
  Top Layer w0.15: U35.7@73.855,167.504 74.125,167.774 R169.1@74.125,169.254
  Top Layer w0.5: R172.2@73.18,169.254 R169.1@74.125,169.254
NetR170_1: R170.1 R171.2 U36.7 | length 2.8
  Top Layer w0.15: U36.7@79.66,163.167 79.93,163.437 R170.1@79.93,164.917
  Top Layer w0.5: R171.2@78.985,164.917 R170.1@79.93,164.917
NetR190_2: R190.2 R194.1 U41.9 X65.1 | length 32.8
  Top Layer w0.15: U41.9@146.423,51.25 v1(147.085,51.25)
  Bottom Layer w0.15: v1(147.085,51.25) 146.275,50.44 146.275,48.673 147.248,47.7 149.082,47.7 151.082,49.7 154.297,49.7 160.067,55.471 R190.2@163.485,55.471 R194.1@163.485,56.758 163.535,56.758 164.285,56.008 168.917,56.008 X65.1@169.9,55.025
NetR192_2: R192.2 U79.1 | length 7.4
  Top Layer w0.15: v1(232.85,174.725) R192.2@232.85,175.675
  Bottom Layer w0.15: U79.1@229.954,170.021 229.983,170.05 230.835,170.05 231.575,170.79 231.575,173.45 v1(232.85,174.725)
NetR212_2: R212.2 U78.1 | length 5.3
  Top Layer w0.15: R212.2@232.825,177.375 v1(232.825,178.325)
  Bottom Layer w0.15: U78.1@229.954,181.137 230.506,181.137 232.825,178.818 v1(232.825,178.325)
NetR214_2: R214.2 U79.4 | length 4.5
  Top Layer w0.15: v1(230.792,170.75) R214.2@232.85,170.75
  Bottom Layer w0.15: U79.4@229.132,171.696 229.132,171.053 229.435,170.75 v1(230.792,170.75)
NetR217_1: R217.1 R218.1 R439.2 U80.3 X16.1 | length 8.9
  Top Layer w0.15: U80.3@219.505,180.767 221.575,180.767 221.625,180.767 221.775,180.617 222.05,180.342 222.05,180.242 223.2,179.092 R439.2@223.25,179.092 ; R218.1@221.6,180.792 X16.1@221.6,182.717 R217.1@224.075,182.717
NetR221_2: R221.2 R224.2 U54.7 | length 7.8
  Top Layer w0.15: R221.2@72.62,146.61 R224.2@74.37,146.61 ; R224.2@74.37,146.56 75.48,145.45 76.996,145.45 77.37,145.077 U54.7@77.37,142.663
NetR222_2: R222.2 R225.2 U54.6 | length 5.7
  Top Layer w0.15: R225.2@76.12,146.61 R222.2@77.87,146.61 U54.6@77.87,142.663
NetR223_2: R223.2 R226.2 U54.5 | length 6.2
  Top Layer w0.15: U54.5@78.37,142.663 78.37,144.331 79.62,145.581 R223.2@79.62,146.61 81.32,146.61 R226.2@81.37,146.66
NetR227_1: R227.1 X73.1 XB1.2 | length 22.3
  Top Layer w0.25: X73.1@81.5,11.676 R227.1@83.085,11.676
  Bottom Layer w0.25: XB1.2@68.3,8.8 68.3,11.5 70.9,14.1 79.076,14.1 X73.1@81.5,11.676 ; XB1.2@81.5,8.8 X73.1@81.5,11.5
NetR228_1: R228.1 R229.1 R230.2 U56.C2 | length 7
  Top Layer w0.15: U56.C2@216.75,94.35 216.788,94.312 216.882,94.312 217.403,93.79 219.108,93.79 219.368,94.05 R230.2@220.25,94.05 220.343,93.957 220.343,92.818 R228.1@220.25,92.725 R229.1@222,92.725
NetR232_2: R232.2 R235.2 U55.1 | length 10.3
  Top Layer w0.15: R232.2@76.7,42.2 76.7,41.373 79.673,38.4 U55.1@81.275,38.4 82.55,38.4 82.925,38.775 82.925,39.525 83.7,40.3 R235.2@83.75,40.3
NetR233_2: R233.2 R236.2 U55.2 | length 10
  Top Layer w0.15: R233.2@78.3,42.2 78.3,40.3 79.55,39.05 U55.2@81.275,39.05 82.3,39.05 82.55,39.3 82.55,40.85 83.275,41.575 83.275,41.625 83.7,42.05 R236.2@83.75,42.05
NetR234_2: R234.2 R237.2 U55.3 | length 8.7
  Top Layer w0.15: U55.3@81.275,39.7 79.825,39.7 79.5,40.025 79.5,41 79.95,41.45 R234.2@79.95,42.2 81.355,42.2 82.955,43.8 R237.2@83.75,43.8
NetR251_2: R251.2 R253.2 U58.12 | length 5.9
  Top Layer w0.15: R251.2@155.024,46.933 155.024,45.298 155.074,45.298 155.514,44.858 155.514,44.808 155.998,44.324 155.998,42.768 156.148,42.618 U58.12@157.237,42.618
NetR252_2: R252.2 R254.2 U58.13 | length 3.9
  Top Layer w0.15: R252.2@155.024,43.633 R254.2@155.024,41.983 U58.13@157.237,41.983
NetR255_2: R255.2 S2.1 S2.4 | length 8.8
  Top Layer w0.15: S2.1@231.425,38.165 237.925,38.165 R255.2@237.925,35.825
NetR258_2: R258.2 S4.1 S4.4 | length 9
  Top Layer w0.15: S4.1@231.425,50.715 S4.1@231.75,50.715 S4.4@237.6,50.715 237.925,50.715 R258.2@237.925,48.225
NetR260_2: R260.2 S1.1 S1.4 | length 8.8
  Top Layer w0.15: S1.1@240.175,38.165 246.675,38.165 R260.2@246.675,35.825
NetR262_2: R262.2 S3.1 S3.4 | length 8.8
  Top Layer w0.15: S3.1@240.175,50.715 246.675,50.715 R262.2@246.675,48.375
NetR272_1: R272.1 R273.1 U58.2 | length 17.6
  Top Layer w0.15: U58.2@162.637,40.712 165.152,40.712 168.556,37.309 168.556,32.388 170.2,30.744 R273.1@170.2,29 R272.1@168.875,29
NetR284_1: R284.1 R285.2 U61.9 | length 3.8
  Top Layer w0.15: U61.9@99.664,63.314 R285.2@100.864,63.314 100.839,63.289 100.839,62.364 101.239,61.964 R284.1@101.239,60.939
NetR289_1: R289.1 U65.5 | length 1.8
  Top Layer w0.15: U65.5@36.253,56.725 R289.1@38.1,56.725
NetR290_1: R290.1 U66.5 | length 1.8
  Top Layer w0.15: U66.5@36.248,38.31 R290.1@38.095,38.31
NetR291_2: R291.2 U65.4 | length 1.9
  Top Layer w0.15: U65.4@36.253,55.455 38.07,55.455 R291.2@38.1,55.425
NetR292_2: R292.2 U66.4 | length 1.9
  Top Layer w0.15: U66.4@36.248,37.04 38.065,37.04 R292.2@38.095,37.01
NetR297_2: R297.2 U78.4 | length 12.9
  Top Layer w0.15: v1(231.139,181.75) 231.211,181.678 231.211,173.914 232.8,172.325 R297.2@232.85,172.325
  Bottom Layer w0.15: U78.4@229.132,182.812 229.132,182.233 229.615,181.75 v1(231.139,181.75)
NetR299_2: R299.2 U78.2 | length 2.3
  Top Layer w0.15: R299.2@229.125,178.825 229.15,178.85 v1(229.15,180.05)
  Bottom Layer w0.15: U78.2@229.132,181.137 229.132,180.068 v1(229.15,180.05)
NetR302_2: R302.2 U79.2 | length 8.5
  Top Layer w0.15: v1(226,172.975) R302.2@227.05,172.975
  Bottom Layer w0.15: v1(226,172.975) 226,169.504 226.302,169.203 228.977,169.203 229.132,169.357 U79.2@229.132,170.021
NetR304_2: R304.2 U73.2 | length 1.8
  Top Layer w0.25: U73.2@22.392,121.925 R304.2@24.142,121.925
NetR310_2: R310.2 U73.8 | length 3.4
  Top Layer w0.15: U73.8@22.392,124.925 23.042,124.925 23.217,125.1 23.217,125.925 22.892,126.25 R310.2@22.892,127.425
NetR311_2: R311.2 U73.10 | length 1.6
  Top Layer w0.15: R311.2@21.392,127.425 21.492,127.325 U73.10@21.492,125.825
NetR313_2: R313.2 R333.1 U74.2 | length 9.2
  Top Layer w0.15: U74.2@32.85,161.85 v1(32.85,163.175)
  Top Layer w0.25: R313.2@28.6,158.45 R333.1@29.625,158.45 v1(29.625,159.225)
  INT2_SIG w0.25: v1(29.625,159.225) 29.625,161.325 31.475,163.175 v1(32.85,163.175)
NetR323_1: R323.1 R326.2 | length 1.7
  Top Layer w0.15: R326.2@39.425,157.873 41.16,157.873 R323.1@41.165,157.868
NetR324_1: R324.1 R327.1 U74.4 | length 6.1
  Top Layer w0.25: U74.4@34.15,161.85 34.15,163.075 34.975,163.9 R324.1@37.6,163.9 R327.1@37.6,162.85
NetR325_2: R325.2 R326.1 U74.5 | length 12.1
  Top Layer w0.15: U74.5@34.8,161.85 34.8,160.9 35.356,160.344 36.03,160.344 37.478,158.896 37.478,158.12 R326.1@37.725,157.873 37.775,157.873 38.807,156.842 38.818,156.842 39.425,156.235 39.425,154.75 38.216,153.541 R325.2@37.3,153.541
NetR328_1: R328.1 R331.1 U75.6 | length 7.3
  Top Layer w0.15: U75.6@29.975,180.35 30.625,180.35 31.375,179.6 31.375,177.174 32.125,176.424 R331.1@32.125,176.374 32.125,175.224 31.5,174.599 R328.1@31.5,174.549
NetR329_2: R329.2 R330.2 U75.5 | length 6.5
  Top Layer w0.15: U75.5@29.475,180.35 29.475,179.52 29.886,179.109 29.886,177.406 30.237,177.055 30.237,176.763 R330.2@30.625,176.375 30.325,176.075 30.325,175.688 30,175.362 R329.2@30,174.55
NetR334_2: R334.2 R388.2 U75.1 | length 7.1
  Top Layer w0.15: R334.2@25.725,176.053 25.75,176.078 26.262,176.078 26.35,176.166 26.35,179.725 26.975,180.35 U75.1@27.475,180.35
  Top Layer w0.25: R388.2@25.725,174.553 R334.2@25.725,176.053
NetR335_1: R335.1 R336.2 | length 3.3
  Top Layer w0.5: R336.2@31.7,143.33 R335.1@31.7,146.625
NetR337_1: R337.1 R338.2 U75.2 | length 6.1
  Top Layer w0.15: R338.2@27.25,176.4 27.975,177.125 U75.2@27.975,180.35
  Top Layer w0.25: R337.1@27.225,174.553 R338.2@27.225,176.403
NetR339_2: R339.2 U75.11 | length 1.6
  Top Layer w0.15: U75.11@30.775,183.15 R339.2@32.4,183.15
NetR342_1: R342.1 U75.4 | length 2.3
  Top Layer w0.15: U75.4@28.975,180.35 28.975,178.225 R342.1@29.125,178.075
NetR345_2: R345.2 R346.1 U76.7 | length 6
  Top Layer w0.15: U76.7@179.1,179.679 179.1,180.315 179.375,180.59 181.43,180.59 182.55,181.71 R346.1@182.6,181.71 R345.2@182.6,183.035
NetR348_2: R348.2 U76.8 | length 1.6
  Top Layer w0.15: U76.8@178.6,179.679 178.6,180.875 R348.2@178.875,181.15
NetR349_2: R349.2 U76.9 | length 1.6
  Top Layer w0.15: R349.2@177.855,181.15 178.1,180.905 U76.9@178.1,179.679
NetR353_1: R353.1 U27.53 | length 2.8
  Top Layer w0.15: U27.53@102.995,164.693 103.02,164.668 104.011,164.668 104.079,164.6 104.455,164.6 104.993,165.138 R353.1@105.561,165.138
NetR378_2: R378.2 U41.2 X111.1 | length 35.8
  Top Layer w0.15: R378.2@142.121,49.885 v1(142.121,50.638) 142.835,50.638 142.923,50.725 U41.2@142.923,51.25
  Bottom Layer w0.15: v1(142.121,50.638) 142.121,49.629 144.532,47.218 149.283,47.218 151.283,49.218 154.423,49.218 159.605,54.4 167.51,54.4 X111.1@169.875,52.035
NetR379_2: R379.2 U96.2 X112.1 | length 5.1
  Top Layer w0.15: X112.1@109.101,171.4 109.101,170.313 R379.2@109.499,169.914
  Bottom Layer w0.15: U96.2@107.71,174.275 107.71,172.791 X112.1@109.101,171.4
NetR382_1: R382.1 U77.15 | length 1.5
  Top Layer w0.15: R382.1@162.275,179 162.65,179.375 U77.15@162.65,180.375
NetR385_1: R385.1 U77.14 | length 1.6
  Top Layer w0.15: R385.1@161.35,179 161.875,179.525 161.938,179.525 162.15,179.737 U77.14@162.15,180.185
NetR386_1: R386.1 U95.3 | length 6.8
  Top Layer w0.15: U95.3@112.516,175.211 115.073,175.211 115.173,175.31 v1(115.294,175.31) ; R386.1@115.375,173.735 115.425,173.735 116.931,175.241 v1(116.993,175.241)
  Bottom Layer w0.15: v1(115.294,175.31) 115.363,175.241 v1(116.993,175.241)
NetR387_1: R387.1 U95.4 | length 1.3
  Top Layer w0.15: U95.4@112.116,175.211 112.116,175.982 R387.1@112.495,176.361
NetR389_1: R389.1 U95.5 | length 2.4
  Top Layer w0.15: U95.5@111.716,175.211 111.716,176.526 R389.1@112.495,177.305
NetR391_1: R391.1 U95.6 X102.1 | length 10.5
  Top Layer w0.15: U95.6@111.316,175.211 111.316,177.026 111.97,177.68 111.97,177.698 112.101,177.83 112.12,177.83 113.064,178.774 113.064,180.455 114.324,181.716 114.543,181.716 115.239,182.411 X102.1@115.239,182.432 R391.1@116.795,182.432
NetR392_2: R392.2 R435.1 U97.3 X103.1 | length 15.5
  Top Layer w0.15: v1(120.47,176.881) 120.477,176.874 120.477,175.725 X103.1@120.484,175.718 121.627,174.575 121.997,174.575 R435.1@122.161,174.411 ; R392.2@122.15,172.843 R435.1@122.15,174.15 ; v1(126.446,183.271) 126.458,183.258 U97.3@126.458,182.348
  Bottom Layer w0.15: v1(120.47,176.881) 121.245,177.656 121.245,179.736 124.78,183.271 v1(126.446,183.271)
NetR394_1: R394.1 R401.2 U95.11 | length 3.2
  Top Layer w0.15: R394.1@110.627,171.793 110.634,171.8 R401.2@111.6,171.8 112.248,172.448 112.248,173.198 112.141,173.305 112.141,173.686 U95.11@112.116,173.711
NetR405_1: R405.1 U97.5 | length 1.5
  Top Layer w0.15: R405.1@122.321,181.4 123.856,181.4 U97.5@123.858,181.398
NetR408_1: R408.1 U85.8 | length 8.7
  Top Layer w0.15: U85.8@213.121,142.425 215.2,142.425 217.8,139.825 R408.1@217.8,136.86
NetR433_1: R433.1 R434.1 R435.2 X101.1 | length 3.9
  Top Layer w0.15: R434.1@117.795,175.611 R433.1@118.749,175.611 118.749,174.383 X101.1@118.737,174.371 118.808,174.3 R435.2@120.45,174.3
NetR440_2: R440.2 R441.2 U80.5 | length 2.6
  Top Layer w0.15: R440.2@214.375,179.817 R441.2@215.375,179.817 U80.5@216.995,179.817
NetR444_2: R444.2 U83.7 U83.8 | length 6.2
  Top Layer w0.15: R444.2@236.5,120.925 237.25,120.175 238.625,120.175 238.875,119.925 238.875,119.617 ; U83.7@237.645,118.9 238.7,118.9 238.875,119.075 238.875,119.617 ; U83.8@237.645,119.55 238.808,119.55 238.875,119.617
NetR470_1: R470.1 U85.4 | length 2.5
  Top Layer w0.15: U85.4@219.021,140.475 220.211,140.475 220.392,140.656 R470.1@221.484,140.656
NetR473_1: R473.1 U85.2 | length 2.6
  Top Layer w0.15: U85.2@219.021,139.175 220.033,139.175 220.477,138.731 R473.1@221.484,138.731
NetR474_1: R474.1 U85.1 | length 2.8
  Top Layer w0.15: U85.1@219.021,138.525 220.111,138.525 220.855,137.781 R474.1@221.484,137.781
NetR475_1: R475.1 U85.3 | length 2.5
  Top Layer w0.15: U85.3@219.021,139.825 220.284,139.825 220.428,139.681 R475.1@221.484,139.681
NetR476_1: R476.1 U85.11 | length 4.8
  Top Layer w0.15: U85.11@213.121,140.475 214.081,140.475 214.672,139.884 R476.1@214.672,136.86
NetRA4_3: RA4.3 U27.39 | length 6.2
  Top Layer w0.15: U27.39@100.994,159.891 100.994,159.09 101.522,158.562 101.522,157.808 102.082,157.249 102.082,156.275 101.845,156.038 101.845,155.035 101.995,154.885 102.506,154.885 RA4.3@102.532,154.859
NetRA4_4: RA4.4 U27.38 | length 7.2
  Top Layer w0.15: U27.38@100.594,159.891 100.594,158.944 101.207,158.331 101.207,157.699 101.782,157.124 101.782,156.399 101.545,156.163 101.545,154.49 101.977,154.059 RA4.4@102.532,154.059
NetRA5_1: RA5.1 U56.D5 | length 4.5
  Top Layer w0.15: U56.D5@213.75,95.35 213.03,96.07 213.03,97.088 213.925,97.982 213.925,99.1 RA5.1@213.95,99.125
NetRA5_2: RA5.2 U56.E3 | length 3.2
  Top Layer w0.15: RA5.2@214.75,99.125 214.725,99.1 214.725,98 215.75,96.975 U56.E3@215.75,96.35
NetRA6_1: RA6.1 U56.E2 | length 2.9
  Top Layer w0.15: RA6.1@216.45,99.125 216.425,99.1 216.425,97.851 216.75,97.526 U56.E2@216.75,96.35
NetRA6_2: RA6.2 U56.E1 | length 3
  Top Layer w0.15: RA6.2@217.25,99.125 217.188,99.063 217.188,97.325 217.713,96.8 217.713,96.387 U56.E1@217.75,96.35
NetU22_1: U22.1 X37.1 | length 6.2
  Top Layer w0.15: X37.1@149.396,181.19 150.071,180.515 150.071,178.516 151.075,177.512 151.075,176.686 151.246,176.515 U22.1@152.046,176.515
NetU22_2: U22.2 X36.1 | length 5
  Top Layer w0.15: X36.1@148.88,179.35 148.88,179.283 150.775,177.388 150.775,176.561 151.221,176.115 U22.2@152.046,176.115
NetU22_9: U22.9 X33.1 | length 4.6
  Top Layer w0.15: X33.1@154.355,170.447 154.355,172.849 154.746,173.24 U22.9@154.746,174.915
NetU37_18: U37.18 X59.1 | length 4.5
  Bottom Layer w0.15: U37.18@86.45,176.25 86.479,176.221 86.659,176.221 86.975,175.905 86.975,175.296 87.986,174.285 88.738,174.285 X59.1@89.5,173.523
NetU56_A5: U56.A5 X76.1 | length 2.9
  Top Layer w0.15: X76.1@211.453,93.85 212.953,92.35 U56.A5@213.75,92.35
NetU59_3: U59.3 U61.3 | length 6.2
  Top Layer w0.15: U61.3@96.414,56.814 96.414,55.503 98.289,53.628 98.289,52.639 97.949,52.3 U59.3@97.187,52.3
NetU59_6: U59.6 U61.4 | length 9.7
  Top Layer w0.15: v1(95.999,50.825) 96.012,50.813 97.174,50.813 U59.6@97.187,50.8 ; U61.4@97.064,56.814 97.064,55.277 98.589,53.753 98.589,52.041 v1(98.548,52)
  INT2_SIG w0.15: v1(95.999,50.825) 97.174,52 v1(98.548,52)
NetU59_10: U59.10 U61.5 | length 8
  Top Layer w0.15: U61.5@97.714,56.814 97.714,55.487 99.113,54.088 99.113,50.737 99.55,50.3 U59.10@100.263,50.3
NetU59_13: U59.13 U61.6 | length 6.2
  Top Layer w0.15: U61.6@98.364,56.814 98.364,55.261 99.413,54.212 99.413,51.888 99.5,51.8 U59.13@100.263,51.8
NetU67_6: U67.6 U70.4 | length 3.1
  Top Layer w0.15: U70.4@25.181,49.605 25.816,49.605 26.058,49.363 26.058,49.347 27.07,48.335 U67.6@27.705,48.335
NetU67_7: U67.7 U70.1 | length 3.1
  Top Layer w0.15: U70.1@25.181,45.795 25.816,45.795 26.058,46.038 26.058,46.053 27.07,47.065 U67.7@27.705,47.065
NetU68_6: U68.6 U69.4 | length 3.1
  Top Layer w0.15: U69.4@25.181,31.188 25.816,31.188 26.058,30.945 26.058,30.93 27.07,29.918 U68.6@27.705,29.918
NetU68_7: U68.7 U69.1 | length 3.1
  Top Layer w0.15: U69.1@25.181,27.378 25.816,27.378 26.058,27.62 26.058,27.636 27.07,28.648 U68.7@27.705,28.648
NetU74_1: U74.1 U74.6 | length 6.5
  Top Layer w0.15: v1(31.525,161.85) U74.1@32.2,161.85 ; U74.6@35.45,161.85 v1(35.45,163.175)
  INT2_SIG w0.15: v1(31.525,161.85) 34.125,161.85 v1(35.45,163.175)
NetU74_8: U74.8 U74.14 | length 6.5
  Top Layer w0.15: U74.14@32.2,167.55 32.2,168.55 32.4,168.75 33.025,168.75 33.59,169.315 35.319,169.315 36.1,168.534 U74.8@36.1,167.55
NetU74_10: U74.10 U74.13 | length 5.3
  Top Layer w0.15: U74.13@32.85,167.55 32.85,165.875 33.075,165.65 34.25,165.65 34.8,166.2 U74.10@34.8,167.55
NetU84_4: U84.4 U84.7 | length 0.8
  Top Layer w0.15: U84.7@139.1,188.283 U84.4@139.1,189.117
NetU84_5: U84.5 U84.6 | length 0.8
  Top Layer w0.15: U84.6@138.6,188.283 U84.5@138.6,189.117
OSPI_1_IO4: M1.B70 RA23.1 | length 6.9
  Top Layer w0.15: v1(112.609,82.071) 112.613,82.076 112.613,82.696 M1.B70@112.617,82.7
  Bottom Layer w0.15: RA23.1@112.4,88.25 112.4,86.8 112.45,86.75 112.45,83.057 112.6,82.907 112.6,82.08 v1(112.609,82.071)
OSPI_1_IO4_JMP: J4.17 J4B.9 RA5.4 | length 28.1
  Top Layer w0.15: J4B.9@202.17,102.12 205.052,102.12 205.127,102.12 205.247,102.24 205.247,102.76 205.367,102.88 205.727,102.88 205.847,102.76 205.847,101.656 205.967,101.536 206.327,101.536 206.447,101.656 206.447,102.76 206.567,102.88 206.927,102.88 207.047,102.76 207.047,101.656 207.167,101.536 207.527,101.536 207.647,101.656 207.647,102.76 207.767,102.88 208.127,102.88 208.247,102.76 208.247,101.656 208.367,101.536 208.727,101.536 208.847,101.656 208.847,102.76 208.967,102.88 209.327,102.88 209.447,102.76 209.447,101.656 209.567,101.536 209.927,101.536 210.047,101.656 210.047,102.506 210.167,102.626 210.527,102.626 210.647,102.506 210.647,102.24 210.767,102.12 211.531,102.12 213.03,102.12 213.95,101.2 RA5.4@213.95,100.725
  Bottom Layer w0.15: J4.17@197.09,102.12 J4B.9@202.17,102.12
OSPI_1_IO5: M1.B71 RA23.2 | length 8.9
  Top Layer w0.15: M1.B71@111.982,82.7 111.982,81.65 112.275,81.357 v1(112.275,81.235)
  Bottom Layer w0.15: RA23.2@111.9,88.25 111.9,86.045 112,85.945 112,83.056 111.877,82.932 111.877,81.634 v1(112.275,81.235)
OSPI_1_IO5_JMP: J4.19 J4B.10 RA5.3 | length 29.3
  Top Layer w0.15: J4B.10@202.17,104.66 204.528,104.66 204.603,104.66 204.723,104.78 204.723,105.339 204.843,105.459 205.203,105.459 205.323,105.339 205.323,104.357 205.443,104.237 205.803,104.237 205.923,104.357 205.923,105.339 206.043,105.459 206.403,105.459 206.523,105.339 206.523,104.357 206.643,104.237 207.003,104.237 207.123,104.357 207.123,105.339 207.243,105.459 207.603,105.459 207.723,105.339 207.723,104.357 207.843,104.237 208.203,104.237 208.323,104.357 208.323,105.339 208.443,105.459 208.803,105.459 208.923,105.339 208.923,104.357 209.043,104.237 209.403,104.237 209.523,104.357 209.523,104.944 209.643,105.064 210.003,105.064 210.123,104.944 210.123,104.78 210.243,104.66 211.36,104.66 212.265,104.66 214.75,102.175 RA5.3@214.75,100.725
  Bottom Layer w0.15: J4.19@197.09,104.66 J4B.10@202.17,104.66
OSPI_1_IO6: M1.B72 RA23.3 | length 7.4
  Top Layer w0.15: M1.B72@111.347,82.7 111.349,82.698 111.349,82.018 v1(111.352,82.016)
  Bottom Layer w0.15: v1(111.352,82.016) 111.352,84.535 110.85,85.037 110.85,86.009 111.4,86.559 RA23.3@111.4,88.25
